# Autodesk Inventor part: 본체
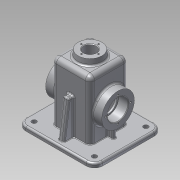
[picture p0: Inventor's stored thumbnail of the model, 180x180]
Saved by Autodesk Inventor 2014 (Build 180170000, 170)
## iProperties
Created: 2016-08
Part Number: 본체
Material: 알루미늄 6061
Document SubType Name: Modeling
Designer: user
Density: 2.71 g/cm^3
Appearance: 알루미늄 - 평지
Mass: 800.305 g
Surface Area: 911.822 cm^2
Volume: 295.316 cm^3
Author: user
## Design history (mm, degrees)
sketch "스케치1"
  geometry: L1 (-65, 57.5)-(65, 57.5); L2 (65, 57.5)-(65, -57.5); L3 (65, -57.5)-(-65, -57.5); L4 (-65, -57.5)-(-65, 57.5); L5 (-65, 57.5)-(65, -57.5); L6 (65, 57.5)-(-65, -57.5); 1 further point
  constraints: 12 end point, 2 midpoint, 2 parallel, 1 horizontal, 1 perpendicular
  dimensions: "d0" = 130 distance of L2.end L3.end; "d1" = 115 distance of L1.end L2.end
extrude "돌출1" new body sketch "스케치1" distance "d2" = 7; taper "d3" = 0 deg
sketch "스케치2"
  geometry: L1 (-32.5, 32.5)-(32.5, 32.5); L2 (32.5, 32.5)-(32.5, -32.5); L3 (32.5, -32.5)-(-32.5, -32.5); L4 (-32.5, -32.5)-(-32.5, 32.5); L5 (-32.5, 32.5)-(32.5, -32.5); L6 (32.5, 32.5)-(-32.5, -32.5); 3 further points
  constraints: 12 end point, 3 midpoint, 2 parallel, 1 coincident, 1 horizontal, 1 perpendicular
  dimensions: "d4" = 65 distance of L2.end L3.end; "d5" = 65 distance of L1.end L2.end
extrude "돌출2" join sketch "스케치2" distance "d6" = 100; taper "d7" = 0 deg
sketch "스케치3"
  geometry: L1 (60, -52.5)-(-60, -52.5); L2 (-60, -52.5)-(-60, 52.5); L3 (-60, 52.5)-(60, 52.5); L4 (60, 52.5)-(60, -52.5); L5 (60, -52.5)-(-60, 52.5); L6 (-60, -52.5)-(60, 52.5); 1 further point
  constraints: 12 end point, 2 midpoint, 2 parallel, 1 horizontal, 1 perpendicular
  dimensions: "d8" = 120 distance of L2.end L3.end; "d9" = 105 distance of L1.end L2.end
extrude "돌출3" join sketch "스케치3" distance "d10" = 3; taper "d11" = 0 deg
sketch "스케치5"
  geometry: L1 (27.5, -27.5)-(-27.5, -27.5); L2 (-27.5, -27.5)-(-27.5, 27.5); L3 (-27.5, 27.5)-(27.5, 27.5); L4 (27.5, 27.5)-(27.5, -27.5); L5 (27.5, -27.5)-(-27.5, 27.5); L6 (-27.5, -27.5)-(27.5, 27.5); 1 further point
  constraints: 12 end point, 2 midpoint, 2 parallel, 1 horizontal, 1 perpendicular
  dimensions: "d13" = 55 distance of L2.end L3.end; "d14" = 55 distance of L1.end L2.end
extrude "돌출4" cut sketch "스케치5" distance "d15" = 105; taper "d16" = 0 deg
sketch "스케치6"
  geometry: L1 (0, 0)-(-100, 0) reference; L2 (10, 85)-(10, -20) reference; C1 r 27.5 at (-45, 32.5); 1 further point
  constraints: 1 centre point
  dimensions: "d17" = 55 diameter of C1; "d18" = 32.5 distance from line of L1 C1.centre; "d19" = 55 distance from line of C1.centre L2
extrude "돌출5" join sketch "스케치6" distance "d20" = 15; taper "d21" = 0 deg
sketch "스케치7" dims "d22" = 42
  geometry: C1 r 27.5 at (0, 0) reference; 3 further points
  constraints: 2 horizontal alignment, 1 coincident, 2 other
hole "구멍1" sketch "스케치7" at (-21, 0) diameter "d23" = 3.242; stored, may be unused: countersink angle "d27" = 90 deg, drill point angle "d29" = 118 deg; dims "d24" = 8, "d25" = 4, "d26" = 2, "d28" = 10
sketch "스케치8"
  geometry: C1 r 27.5 at (0, 0) reference; C2 r 17.5 at (0, 0); 1 further point
  constraints: 1 centre point, 1 coincident
  dimensions: "d33" = 35 diameter of C2
extrude "돌출6" cut sketch "스케치8" distance "d34" = 17; taper "d35" = 0 deg
sketch "스케치9"
  geometry: C1 r 17.5 at (0, 0) reference; C2 r 15 at (0, 0); 1 further point
  constraints: 1 centre point, 1 coincident
  dimensions: "d36" = 30 diameter of C2
extrude "돌출7" cut sketch "스케치9" stored distance "d37" = 0; taper "d38" = 0 deg
sketch "스케치10"
  geometry: L1 (-32.5, 7)-(-32.5, 107) reference; L2 (65, 7)-(-65, 7) reference; L3 (-32.5, 24.5)-(-47.5, 24.5) reference; L4 (-42.5, 7)-(-42.5, 24.5); 2 further points
  constraints: 2 end point, 2 point on line, 1 perpendicular
  dimensions: "d39" = 15 horizontal distance of L4.start point (-27.5, -3)
feature "리브1" sketch "스케치10" dims "d40" = 1, "d41" = 6, "d42" = 0, "d43" = 0, "d44" = 1, "d45" = 1
node "작업 평면1"
sketch "스케치12"
  geometry: C1 r 20 at (0, 0); 1 further point
  constraints: 1 centre point, 1 coincident
  dimensions: "d47" = 40 diameter of C1
extrude "돌출8" join sketch "스케치12" stored distance "d48" = 17; taper "d49" = 7 deg
sketch "스케치13"
  geometry: C1 r 10.5 at (0, 0); 1 further point
  constraints: 1 centre point, 1 coincident
  dimensions: "d50" = 21 diameter of C1
extrude "돌출9" cut sketch "스케치13" stored distance "d51" = 17; taper "d52" = 0 deg
sketch "스케치14" dims "d53" = 29
  geometry: 3 further points
  constraints: 2 horizontal alignment, 1 coincident, 2 other
hole "구멍2" sketch "스케치14" at (14.5, 0) diameter "d54" = 2.459; stored, may be unused: countersink angle "d58" = 90 deg, drill point angle "d60" = 118 deg; dims "d55" = 7, "d56" = 4, "d57" = 2, "d59" = 9
sketch "스케치15"
  geometry: L1 (-49.5, 7)-(-41.068, 67); L2 (-57.5, 0)-(-57.5, 7) reference; L3 (57.5, 7)-(-57.5, 7) reference; L4 (-52.5, -3)-(52.5, -3) reference; L5 (-32.5, 7)-(-32.5, 107) reference; L6 (-41.068, 67)-(-32.5, 67); 1 further point
  constraints: 4 end point, 2 point on line, 1 perpendicular
  dimensions: "d64" = 8 distance of L2.end L1.start; "d65" = 70 distance from line of L1.end L4; "d66" = 98 deg angle of L1 L3
feature "리브2" sketch "스케치15" dims "d67" = 1, "d68" = 10, "d69" = 0, "d70" = 0, "d71" = 1, "d72" = 1
fillet "모깎기1" dims "d73" = 14
fillet "모깎기2" dims "d74" = 9
sketch "스케치17"
  geometry: L1 (-51, -52.5)-(51, -52.5) reference; L2 (-60, 43.5)-(-60, -43.5) reference; 2 further points
  dimensions: "d75" = 9 distance from line of L1 point (-51, -43.5); "d76" = 9 distance from line of L2 point (-51, -43.5)
hole "구멍3" sketch "스케치17" at (-51, -43.5) diameter "d77" = 8; stored, may be unused: countersink angle "d81" = 90 deg, drill point angle "d83" = 118 deg; dims "d78" = 7, "d79" = 4, "d80" = 2, "d82" = 9
sketch "스케치18"
  geometry: L1 (0, 65)-(0, 0) reference; L2 (-100, 65)-(0, 65) reference; L3 (10, 52.5)-(10, 12.5) reference; 3 further points
  constraints: 1 midpoint, 1 other
  dimensions: "d91" = 26 distance from line of L3 point (-16, 32.5); "d92" = 32.5 distance from line of L2 point (-16, 32.5)
feature "엠보싱1" sketch "스케치18" dims "d93" = 0.5, "d94" = 0
fillet "모깎기3" dims "d95" = 8
fillet "모깎기4" dims "d96" = 8
fillet "모깎기5" dims "d97" = 0.3
chamfer "모따기1" distance "d98" = 1; stored, may be unused: second distance "d99" = 2, angle "d100" = 45 deg
chamfer "모따기2" distance "d101" = 1; stored, may be unused: second distance "d102" = 2, angle "d103" = 45 deg
fillet "모깎기6" dims "d104" = 3
fillet "모깎기7" dims "d105" = 3
fillet "모깎기8" dims "d106" = 3
fillet "모깎기9" dims "d107" = 3
fillet "모깎기10" dims "d108" = 3
fillet "모깎기11" dims "d109" = 3
fillet "모깎기12" dims "d110" = 3
fillet "모깎기13" dims "d111" = 1
fillet "모깎기14" dims "d112" = 3
fillet "모깎기15" dims "d113" = 3
fillet "모깎기16" dims "d114" = 3
node "솔리드1"
pattern_circular "원형 패턴1" dims angle "d31" = 360 deg
pattern_circular "원형 패턴2" dims angle "d62" = 360 deg
mirror "대칭1"
mirror "대칭2"
pattern_linear "직사각형 패턴1" dims "d86" = 87, "d89" = 102
other parameters: "d46" = 117
